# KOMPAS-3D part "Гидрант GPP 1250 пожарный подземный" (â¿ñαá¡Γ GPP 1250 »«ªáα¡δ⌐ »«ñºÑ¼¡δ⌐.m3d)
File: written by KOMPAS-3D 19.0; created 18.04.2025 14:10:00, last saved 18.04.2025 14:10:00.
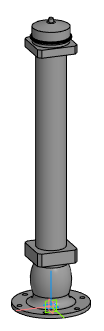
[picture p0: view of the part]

Document properties: Полное имя файла: E:\Dendor Работа Сачек\3D для проекитирвщиков\11.1 Тип GPP. Гидрант пожарный подземный\stp_Тип GPP. 750-6000 Гидрант пожарный подземный\Гидрант GPP 1250 пожарный подземный.m3d

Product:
- Part/product: Гидрант GPP 1250 пожарный подземный

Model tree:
1. Операция без истории:1  (labels: Гидрант GPP 1250 пожарный подземный)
